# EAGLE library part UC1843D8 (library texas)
PULSE WIDTH MODULATOR
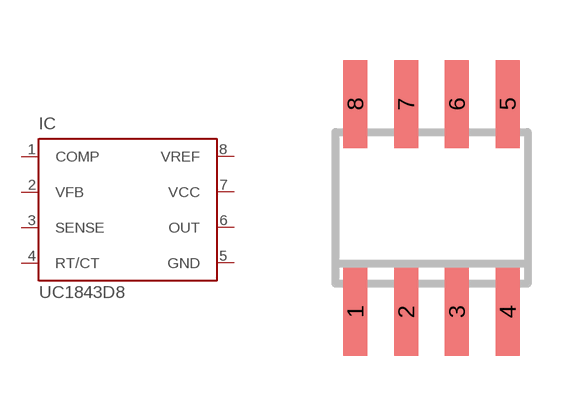
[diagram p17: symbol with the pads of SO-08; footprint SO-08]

Designator prefix IC

## UC1843D8 (MPN: UC1843AMDREP; OC_FARNELL: 1755515; OC_NEWARK: 46M1388)  [SO-08]
1  COMP  pas
2  VFB  in
3  SENSE  in
4  RT/CT  pas
5  GND  pwr
6  OUT  out
7  VCC  pwr
8  VREF  out

## Footprint SO-08 (pad centres in mm)
D (R-PDSO-G8) Plastic Small Outline Package Source: http://focus.ti.com/lit/ds/symlink/sn65als176.pdf
smd 0.6 x 2.2: 1 -1.905,-2.6; 2 -0.635,-2.6; 3 0.635,-2.6; 4 1.905,-2.6; 5 1.905,2.6; 6 0.635,2.6; 7 -0.635,2.6; 8 -1.905,2.6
